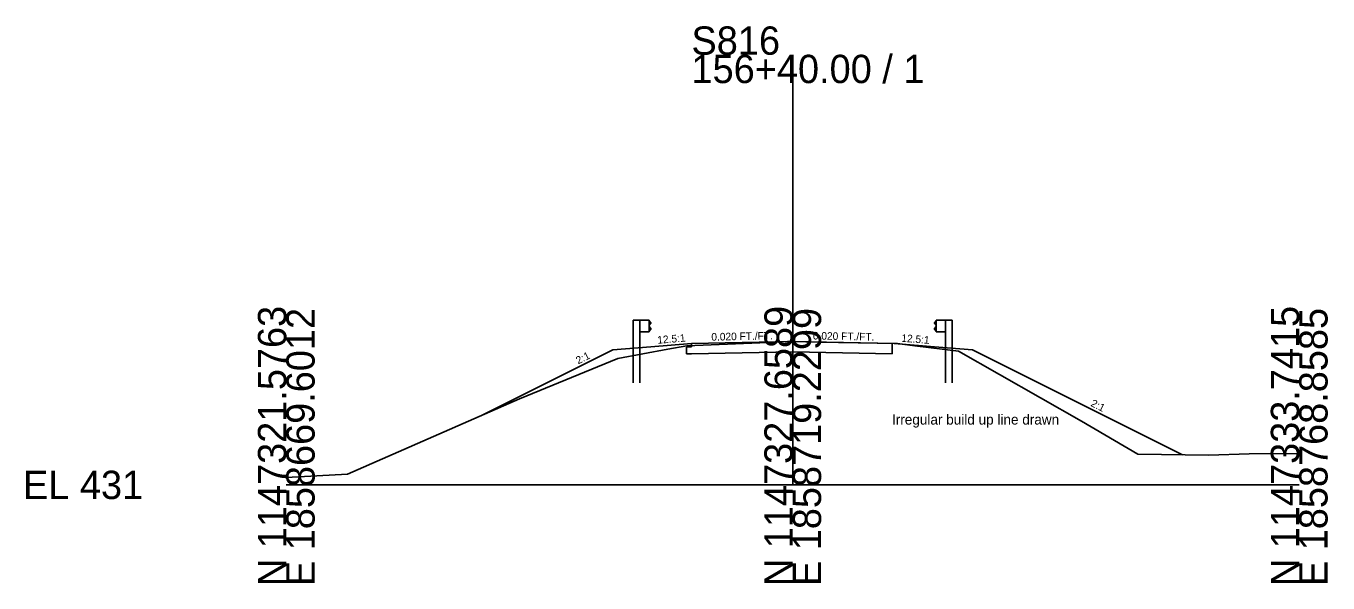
# Model space of a CAD drawing. Extents: x -76 to 4323, y -10 to 2055.
# Drawn here: x 4194.3 to 4322.8, y -9.7 to 45.3 of the extents above; entities that cross this region are included whole.
import ezdxf

# ---------------------------------------------------------------- set-up
doc = ezdxf.new("R2010")
doc.units = 0
for name, color, linetype in [('Default', 7, 'Continuous'), ('RD_GPK_XS_Cell', 7, 'Continuous'), ('RD_XS_Base', 7, 'Continuous'), ('RD_XS_EarthShd', 7, 'Continuous'), ('RD_XS_ExGround', 7, 'Continuous'), ('RD_XS_GR', 7, 'Continuous'), ('RD_XS_Pave', 7, 'Continuous'), ('RD_XS_TieSlope', 7, 'Continuous'), ('RD_XS_TX_ShdSlope', 7, 'Continuous'), ('RD_XS_TX_Slope', 7, 'Continuous'), ('RD_XS_TX_Warning', 7, 'Continuous')]:
    doc.layers.add(name, color=color, linetype=linetype)

msp = doc.modelspace()

# ---------------------------------------------------------------- linework, layer by layer
at = {"layer": 'Default'}
for p, q in [((4260, 13.96), (4270, 14.16)), ((4270, 14.16), (4280, 13.96))]:
    msp.add_line(p, q, dxfattribs=at)
at = {"layer": 'RD_GPK_XS_Cell'}
for p, q in [((4270, 0), (4270, 42.5)), ((4220, 0), (4270, 0)), ((4270, 0), (4320, 0))]:
    msp.add_line(p, q, dxfattribs=at)
at = {"layer": 'RD_XS_Base'}
for p, q in [((4260, 12.96), (4270, 13.16)), ((4270, 13.16), (4279.8, 12.96)), ((4279.8, 12.96), (4279.8, 13.96))]:
    msp.add_line(p, q, dxfattribs=at)
at = {"layer": 'RD_XS_EarthShd'}
for p, q in [((4256, 13.64), (4252.25, 13.34)), ((4256, 13.64), (4252.25, 13.34)), ((4260, 13.96), (4256, 13.64)), ((4260, 13.96), (4256, 13.64)), ((4280, 13.96), (4284, 13.64)), ((4280, 13.96), (4284, 13.64)), ((4284, 13.64), (4287.75, 13.34)), ((4284, 13.64), (4287.75, 13.34))]:
    msp.add_line(p, q, dxfattribs=at)
at = {"layer": 'RD_XS_ExGround'}
msp.add_lwpolyline([(4220, 0.72), (4226.04, 1.05), (4243.01, 8.49), (4252.73, 12.48), (4257.68, 13.41), (4259.55, 13.75), (4266.75, 14.05), (4269.48, 14.17), (4270, 14.16), (4272.59, 14.11), (4280.35, 13.97), (4282.06, 13.75), (4286.36, 13.22), (4298.51, 6.31), (4304.06, 3.04), (4311.09, 2.94), (4315.06, 3.08), (4320, 3.09)], dxfattribs=at)
at = {"layer": 'RD_XS_GR'}
for p, q in [((4254.25, 16.29), (4254.25, 13.5)), ((4254.92, 16.29), (4254.25, 16.29)), ((4254.25, 16.29), (4254.25, 13.5)), ((4254.92, 16.29), (4254.25, 16.29)), ((4254.92, 16.29), (4254.92, 13.55)), ((4255.83, 16.29), (4254.92, 16.29)), ((4254.92, 16.29), (4254.92, 13.55)), ((4255.83, 16.29), (4254.92, 16.29)), ((4255.83, 15.13), (4255.83, 16.29)), ((4255.83, 15.13), (4255.83, 16.29)), ((4255.83, 16.22), (4256, 16.02)), ((4255.83, 16.22), (4256, 16.02)), ((4256, 15.97), (4255.83, 15.77)), ((4256, 15.97), (4255.83, 15.77)), ((4256, 15.45), (4255.83, 15.65)), ((4256, 15.45), (4255.83, 15.65)), ((4256, 16.02), (4256, 15.97)), ((4256, 16.02), (4256, 15.97)), ((4256, 15.4), (4256, 15.45)), ((4256, 15.4), (4256, 15.45)), ((4284.17, 16.22), (4284, 16.02)), ((4284, 16.02), (4284, 15.97)), ((4284, 16.02), (4284, 15.97)), ((4284, 15.97), (4284.17, 15.77)), ((4284, 15.97), (4284.17, 15.77)), ((4284, 15.45), (4284.17, 15.65)), ((4284, 15.45), (4284.17, 15.65)), ((4284, 15.4), (4284, 15.45)), ((4284, 15.4), (4284, 15.45)), ((4284.17, 16.29), (4285.08, 16.29)), ((4284.17, 16.29), (4285.08, 16.29)), ((4284.17, 15.13), (4284.17, 16.29)), ((4284.17, 15.13), (4284.17, 16.29)), ((4285.08, 16.29), (4285.08, 13.55)), ((4285.08, 16.29), (4285.75, 16.29)), ((4285.08, 16.29), (4285.08, 13.55)), ((4285.08, 16.29), (4285.75, 16.29)), ((4285.75, 16.29), (4285.75, 13.5)), ((4285.75, 16.29), (4285.75, 13.5)), ((4255.83, 15.13), (4254.92, 15.13)), ((4255.83, 15.13), (4254.92, 15.13)), ((4255.83, 15.2), (4256, 15.4)), ((4255.83, 15.2), (4256, 15.4)), ((4284.17, 15.2), (4284, 15.4)), ((4284.17, 15.2), (4284, 15.4)), ((4284.17, 15.13), (4285.08, 15.13)), ((4284.17, 15.13), (4285.08, 15.13)), ((4254.25, 13.5), (4254.25, 10.08)), ((4254.25, 13.5), (4254.25, 10.08)), ((4254.92, 10.08), (4254.92, 13.55)), ((4254.92, 10.08), (4254.92, 13.55)), ((4285.08, 10.08), (4285.08, 13.55)), ((4285.75, 13.5), (4285.75, 10.08))]:
    msp.add_line(p, q, dxfattribs=at)
at = {"layer": 'RD_XS_Pave'}
for p, q in [((4259.5, 13.62), (4260, 13.63)), ((4259.5, 12.95), (4259.5, 13.62)), ((4260, 12.96), (4259.5, 12.95)), ((4260, 13.63), (4260, 13.96))]:
    msp.add_line(p, q, dxfattribs=at)
at = {"layer": 'RD_XS_TieSlope'}
for p, q in [((4252.25, 13.34), (4239.35, 6.88)), ((4252.25, 13.34), (4246.71, 10.57)), ((4287.75, 13.34), (4308.47, 2.98))]:
    msp.add_line(p, q, dxfattribs=at)

# ---------------------------------------------------------------- texts
at = {"layer": 'RD_GPK_XS_Cell'}
for s, p in [('S816', (4260, 42.5)), ('156+40.00 / 1', (4260, 39.7)), ('EL 431', (4194, -1.4))]:
    msp.add_text(s, height=2.8, dxfattribs=at).set_placement(p)
for s, p in [('N 1147321.5763', (4220, -10)), ('E 1858669.6012', (4222.8, -10)), ('N 1147327.6589', (4270, -10)), ('E 1858719.2299', (4272.8, -10)), ('N 1147333.7415', (4320, -10)), ('E 1858768.8585', (4322.8, -10))]:
    msp.add_text(s, height=2.8, rotation=90, dxfattribs=at).set_placement(p)
at = {"layer": 'RD_XS_TX_ShdSlope'}
for rotation, p in [(4.5739, (4256.66, 13.94)), (355.4261, (4280.7, 14.15)), (355.4261, (4280.7, 14.15))]:
    msp.add_text('12.5:1', height=0.75, rotation=rotation, dxfattribs=at).set_placement(p)
at = {"layer": 'RD_XS_TX_Slope'}
for s, rotation, p in [('0.020 FT./FT.', 1.1458, (4261.97, 14.25)), ('0.020 FT./FT.', 358.8542, (4271.98, 14.37)), ('2:1', 26.5651, (4248.82, 11.9)), ('2:1', 333.4349, (4299.35, 7.82))]:
    msp.add_text(s, height=0.75, rotation=rotation, dxfattribs=at).set_placement(p)
at = {"layer": 'RD_XS_TX_Warning'}
msp.add_text('Irregular build up line drawn', height=1, dxfattribs=at).set_placement((4279.8, 5.96))

doc.saveas('drawing.dxf')
